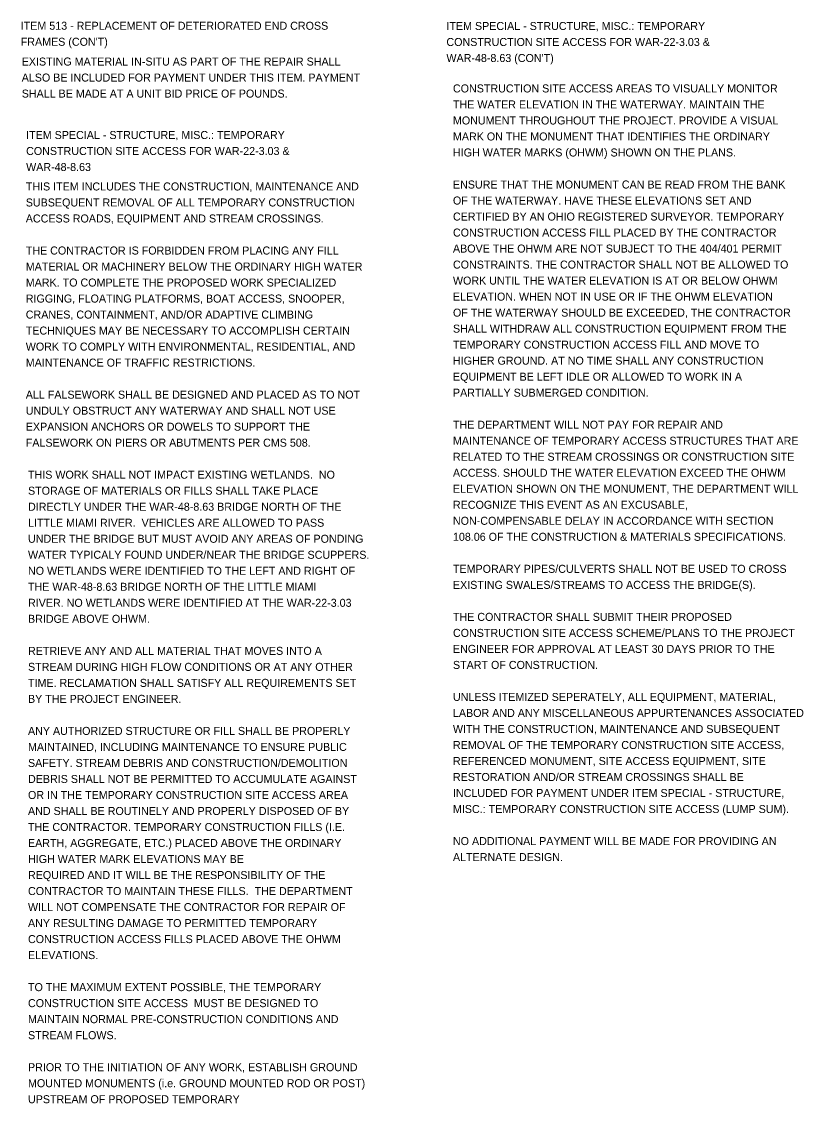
# Model space of a CAD drawing. Extents: x -15 to 144, y -80 to 40.
# Drawn here: x 89.19 to 102.86, y -13.18 to 5.73 of the extents above; entities that cross this region are included whole.
import ezdxf

# ---------------------------------------------------------------- set-up
doc = ezdxf.new("R2010")
doc.units = 0
doc.layers.add('BR_P_Gen_Text', color=7, linetype='Continuous')

msp = doc.modelspace()

# ---------------------------------------------------------------- texts
at = {"layer": 'BR_P_Gen_Text'}
for s, p in [('ITEM 513 - REPLACEMENT OF DETERIORATED END CROSS', (89.175, 5.588)), ('ITEM SPECIAL - STRUCTURE, MISC.: TEMPORARY ', (96.62, 5.584)), ("FRAMES (CON'T)", (89.175, 5.308)), ('CONSTRUCTION SITE ACCESS FOR WAR-22-3.03 & ', (96.62, 5.304)), ("WAR-48-8.63 (CON'T)", (96.62, 5.024)), ('EXISTING MATERIAL IN-SITU AS PART OF THE REPAIR SHALL', (89.192, 4.962)), ('ALSO BE INCLUDED FOR PAYMENT UNDER THIS ITEM. PAYMENT', (89.192, 4.682)), ('SHALL BE MADE AT A UNIT BID PRICE OF POUNDS.', (89.192, 4.402)), ('CONSTRUCTION SITE ACCESS AREAS TO VISUALLY MONITOR ', (96.734, 4.492)), ('THE WATER ELEVATION IN THE WATERWAY. MAINTAIN THE ', (96.734, 4.212)), ('MONUMENT THROUGHOUT THE PROJECT. PROVIDE A VISUAL ', (96.734, 3.932)), ('ITEM SPECIAL - STRUCTURE, MISC.: TEMPORARY ', (89.269, 3.678)), ('MARK ON THE MONUMENT THAT IDENTIFIES THE ORDINARY ', (96.734, 3.652)), ('CONSTRUCTION SITE ACCESS FOR WAR-22-3.03 & ', (89.269, 3.398)), ('HIGH WATER MARKS (OHWM) SHOWN ON THE PLANS.', (96.734, 3.372)), ('WAR-48-8.63', (89.269, 3.118)), ('THIS ITEM INCLUDES THE CONSTRUCTION, MAINTENANCE AND ', (89.263, 2.778)), ('ENSURE THAT THE MONUMENT CAN BE READ FROM THE BANK ', (96.734, 2.812)), ('OF THE WATERWAY. HAVE THESE ELEVATIONS SET AND ', (96.734, 2.532)), ('SUBSEQUENT REMOVAL OF ALL TEMPORARY CONSTRUCTION ', (89.263, 2.498)), ('ACCESS ROADS, EQUIPMENT AND STREAM CROSSINGS.', (89.263, 2.218)), ('CERTIFIED BY AN OHIO REGISTERED SURVEYOR. TEMPORARY ', (96.734, 2.252)), ('CONSTRUCTION ACCESS FILL PLACED BY THE CONTRACTOR ', (96.734, 1.972)), ('THE CONTRACTOR IS FORBIDDEN FROM PLACING ANY FILL ', (89.263, 1.658)), ('ABOVE THE OHWM ARE NOT SUBJECT TO THE 404/401 PERMIT ', (96.734, 1.692)), ('MATERIAL OR MACHINERY BELOW THE ORDINARY HIGH WATER ', (89.263, 1.378)), ('CONSTRAINTS. THE CONTRACTOR SHALL NOT BE ALLOWED TO ', (96.734, 1.412)), ('MARK. TO COMPLETE THE PROPOSED WORK SPECIALIZED ', (89.263, 1.098)), ('WORK UNTIL THE WATER ELEVATION IS AT OR BELOW OHWM ', (96.734, 1.132)), ('RIGGING, FLOATING PLATFORMS, BOAT ACCESS, SNOOPER, ', (89.263, 0.818)), ('ELEVATION. WHEN NOT IN USE OR IF THE OHWM ELEVATION ', (96.734, 0.852)), ('CRANES, CONTAINMENT, AND/OR ADAPTIVE CLIMBING ', (89.263, 0.538)), ('OF THE WATERWAY SHOULD BE EXCEEDED, THE CONTRACTOR ', (96.734, 0.572)), ('TECHNIQUES MAY BE NECESSARY TO ACCOMPLISH CERTAIN ', (89.263, 0.258)), ('SHALL WITHDRAW ALL CONSTRUCTION EQUIPMENT FROM THE ', (96.734, 0.292)), ('WORK TO COMPLY WITH ENVIRONMENTAL, RESIDENTIAL, AND ', (89.263, -0.022)), ('TEMPORARY CONSTRUCTION ACCESS FILL AND MOVE TO ', (96.734, 0.012)), ('MAINTENANCE OF TRAFFIC RESTRICTIONS.', (89.263, -0.302)), ('HIGHER GROUND. AT NO TIME SHALL ANY CONSTRUCTION ', (96.734, -0.268)), ('EQUIPMENT BE LEFT IDLE OR ALLOWED TO WORK IN A ', (96.734, -0.548)), ('ALL FALSEWORK SHALL BE DESIGNED AND PLACED AS TO NOT ', (89.263, -0.862)), ('PARTIALLY SUBMERGED CONDITION.', (96.734, -0.828)), ('UNDULY OBSTRUCT ANY WATERWAY AND SHALL NOT USE ', (89.263, -1.142)), ('EXPANSION ANCHORS OR DOWELS TO SUPPORT THE ', (89.263, -1.422)), ('THE DEPARTMENT WILL NOT PAY FOR REPAIR AND ', (96.734, -1.388)), ('FALSEWORK ON PIERS OR ABUTMENTS PER CMS 508.', (89.263, -1.702)), ('MAINTENANCE OF TEMPORARY ACCESS STRUCTURES THAT ARE ', (96.734, -1.668)), ('RELATED TO THE STREAM CROSSINGS OR CONSTRUCTION SITE ', (96.734, -1.948)), ('THIS WORK SHALL NOT IMPACT EXISTING WETLANDS.  NO ', (89.302, -2.262)), ('ACCESS. SHOULD THE WATER ELEVATION EXCEED THE OHWM ', (96.734, -2.228)), ('STORAGE OF MATERIALS OR FILLS SHALL TAKE PLACE ', (89.302, -2.542)), ('ELEVATION SHOWN ON THE MONUMENT, THE DEPARTMENT WILL ', (96.734, -2.508)), ('RECOGNIZE THIS EVENT AS AN EXCUSABLE, ', (96.734, -2.788)), ('DIRECTLY UNDER THE WAR-48-8.63 BRIDGE NORTH OF THE ', (89.302, -2.822)), ('LITTLE MIAMI RIVER.  VEHICLES ARE ALLOWED TO PASS ', (89.302, -3.102)), ('NON-COMPENSABLE DELAY IN ACCORDANCE WITH SECTION ', (96.734, -3.068)), ('108.06 OF THE CONSTRUCTION & MATERIALS SPECIFICATIONS.', (96.734, -3.348)), ('UNDER THE BRIDGE BUT MUST AVOID ANY AREAS OF PONDING ', (89.302, -3.382)), ('WATER TYPICALY FOUND UNDER/NEAR THE BRIDGE SCUPPERS.  ', (89.302, -3.662)), ('TEMPORARY PIPES/CULVERTS SHALL NOT BE USED TO CROSS ', (96.734, -3.908)), ('NO WETLANDS WERE IDENTIFIED TO THE LEFT AND RIGHT OF ', (89.302, -3.942)), ('THE WAR-48-8.63 BRIDGE NORTH OF THE LITTLE MIAMI ', (89.302, -4.222)), ('EXISTING SWALES/STREAMS TO ACCESS THE BRIDGE(S).', (96.734, -4.188)), ('RIVER. NO WETLANDS WERE IDENTIFIED AT THE WAR-22-3.03 ', (89.302, -4.502)), ('BRIDGE ABOVE OHWM.', (89.302, -4.782)), ('THE CONTRACTOR SHALL SUBMIT THEIR PROPOSED ', (96.734, -4.748)), ('CONSTRUCTION SITE ACCESS SCHEME/PLANS TO THE PROJECT ', (96.734, -5.028)), ('RETRIEVE ANY AND ALL MATERIAL THAT MOVES INTO A ', (89.302, -5.342)), ('ENGINEER FOR APPROVAL AT LEAST 30 DAYS PRIOR TO THE ', (96.734, -5.308)), ('STREAM DURING HIGH FLOW CONDITIONS OR AT ANY OTHER ', (89.302, -5.622)), ('START OF CONSTRUCTION.', (96.734, -5.588)), ('TIME. RECLAMATION SHALL SATISFY ALL REQUIREMENTS SET ', (89.302, -5.902)), ('BY THE PROJECT ENGINEER.', (89.302, -6.182)), ('UNLESS ITEMIZED SEPERATELY, ALL EQUIPMENT, MATERIAL, ', (96.734, -6.148)), ('LABOR AND ANY MISCELLANEOUS APPURTENANCES ASSOCIATED ', (96.734, -6.428)), ('ANY AUTHORIZED STRUCTURE OR FILL SHALL BE PROPERLY ', (89.302, -6.742)), ('WITH THE CONSTRUCTION, MAINTENANCE AND SUBSEQUENT ', (96.734, -6.708)), ('MAINTAINED, INCLUDING MAINTENANCE TO ENSURE PUBLIC ', (89.302, -7.022)), ('REMOVAL OF THE TEMPORARY CONSTRUCTION SITE ACCESS, ', (96.734, -6.988)), ('SAFETY. STREAM DEBRIS AND CONSTRUCTION/DEMOLITION ', (89.302, -7.302)), ('REFERENCED MONUMENT, SITE ACCESS EQUIPMENT, SITE ', (96.734, -7.268)), ('DEBRIS SHALL NOT BE PERMITTED TO ACCUMULATE AGAINST ', (89.302, -7.582)), ('RESTORATION AND/OR STREAM CROSSINGS SHALL BE ', (96.734, -7.548)), ('OR IN THE TEMPORARY CONSTRUCTION SITE ACCESS AREA ', (89.302, -7.862)), ('INCLUDED FOR PAYMENT UNDER ITEM SPECIAL - STRUCTURE, ', (96.734, -7.828)), ('AND SHALL BE ROUTINELY AND PROPERLY DISPOSED OF BY ', (89.302, -8.142)), ('MISC.: TEMPORARY CONSTRUCTION SITE ACCESS (LUMP SUM).', (96.734, -8.108)), ('THE CONTRACTOR. TEMPORARY CONSTRUCTION FILLS (I.E. ', (89.302, -8.422)), ('EARTH, AGGREGATE, ETC.) PLACED ABOVE THE ORDINARY ', (89.302, -8.702)), ('NO ADDITIONAL PAYMENT WILL BE MADE FOR PROVIDING AN ', (96.734, -8.668)), ('HIGH WATER MARK ELEVATIONS MAY BE', (89.302, -8.982)), ('ALTERNATE DESIGN. ', (96.734, -8.948)), ('REQUIRED AND IT WILL BE THE RESPONSIBILITY OF THE ', (89.302, -9.262)), ('CONTRACTOR TO MAINTAIN THESE FILLS.  THE DEPARTMENT ', (89.302, -9.542)), ('WILL NOT COMPENSATE THE CONTRACTOR FOR REPAIR OF ', (89.302, -9.822)), ('ANY RESULTING DAMAGE TO PERMITTED TEMPORARY ', (89.302, -10.102)), ('CONSTRUCTION ACCESS FILLS PLACED ABOVE THE OHWM ', (89.302, -10.382)), ('ELEVATIONS.  ', (89.302, -10.662)), ('TO THE MAXIMUM EXTENT POSSIBLE, THE TEMPORARY ', (89.302, -11.222)), ('CONSTRUCTION SITE ACCESS  MUST BE DESIGNED TO ', (89.302, -11.502)), ('MAINTAIN NORMAL PRE-CONSTRUCTION CONDITIONS AND ', (89.302, -11.782)), ('STREAM FLOWS.', (89.302, -12.062)), ('PRIOR TO THE INITIATION OF ANY WORK, ESTABLISH GROUND ', (89.302, -12.622)), ('MOUNTED MONUMENTS (i.e. GROUND MOUNTED ROD OR POST) ', (89.302, -12.902)), ('UPSTREAM OF PROPOSED TEMPORARY ', (89.302, -13.182))]:
    msp.add_text(s, height=0.14, dxfattribs=at).set_placement(p)

doc.saveas('drawing.dxf')
